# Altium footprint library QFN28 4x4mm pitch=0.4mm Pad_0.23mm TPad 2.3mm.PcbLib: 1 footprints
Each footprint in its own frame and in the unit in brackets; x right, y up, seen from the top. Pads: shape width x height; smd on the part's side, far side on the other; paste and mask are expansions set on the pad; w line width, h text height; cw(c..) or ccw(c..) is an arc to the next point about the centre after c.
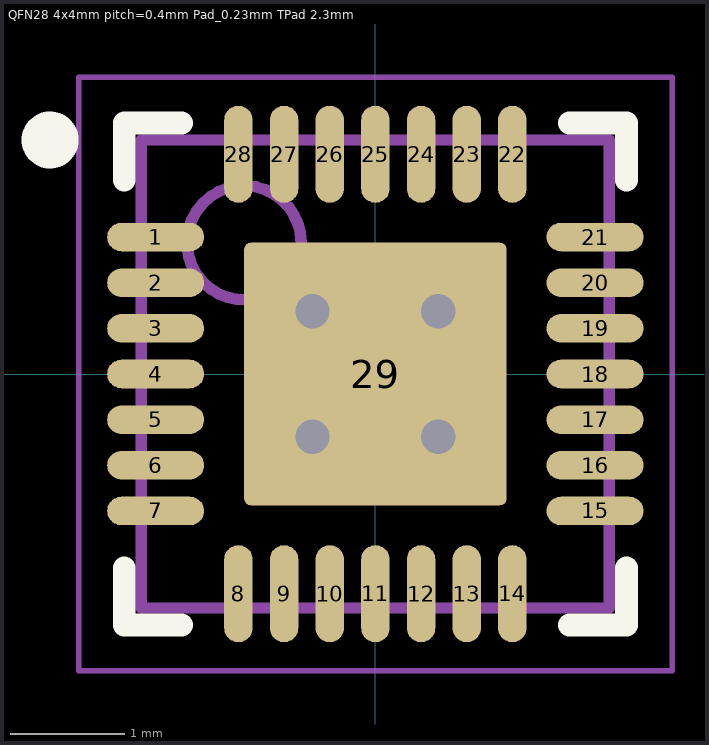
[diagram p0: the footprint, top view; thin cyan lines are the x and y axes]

## QFN28 4x4mm pitch=0.4mm Pad_0.23mm TPad 2.3mm [mm] "QFN, 28-Leads, Body 4.00x4.00mm, Pitch 0.40mm, Thermal Pad 2.60x2.60mm, IPC Medium Density"
height 0.8
pads (29):
  oval 0.85x0.25 smd: 1(-1.925,1.2) 2(-1.925,0.8) 3(-1.925,0.4) 4(-1.925,0) 5(-1.925,-0.4) 6(-1.925,-0.8) 7(-1.925,-1.2) 15(1.925,-1.2) 16(1.925,-0.8) 17(1.925,-0.4) 18(1.925,0) 19(1.925,0.4) 20(1.925,0.8) 21(1.925,1.2)
  oval 0.25x0.85 smd: 8(-1.2,-1.925) 9(-0.8,-1.925) 10(-0.4,-1.925) 11(0,-1.925) 12(0.4,-1.925) 13(0.8,-1.925) 14(1.2,-1.925) 22(1.2,1.925) 23(0.8,1.925) 24(0.4,1.925) 25(0,1.925) 26(-0.4,1.925) 27(-0.8,1.925) 28(-1.2,1.925)
  rrect5% 2.3x2.3 smd: 29(0,0)
via 0.55,-0.55 diameter 0.7 hole 0.3
via -0.55,-0.55 diameter 0.7 hole 0.3
via 0.55,0.55 diameter 0.7 hole 0.3
via -0.55,0.55 diameter 0.7 hole 0.3
Top Overlay:
  circle w0.25: c-2.85,2.05 r0.125
  lines w0.2: -2.2,-1.7 -2.2,-2.2 -1.7,-2.2 ; -2.2,1.7 -2.2,2.2 -1.7,2.2 ; 1.7,-2.2 2.2,-2.2 2.2,-1.7 ; 1.7,2.2 2.2,2.2 2.2,1.7
Mechanical 13:
  circle w0.1: c-1.15,1.15 r0.5
  lines w0.1: -2.05,-2.05 2.05,-2.05 2.05,2.05 -2.05,2.05 -2.05,-2.05
Mechanical 15:
  lines w0.05: -2.6,-2.6 2.6,-2.6 2.6,2.6 -2.6,2.6 -2.6,-2.6
  lines w0.1: -0.5,0 0.5,0 ; 0,-0.5 0,0.5
3D body: height 0.8, standoff 0.05, extent -2.05,-2.05 2.05,2.05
